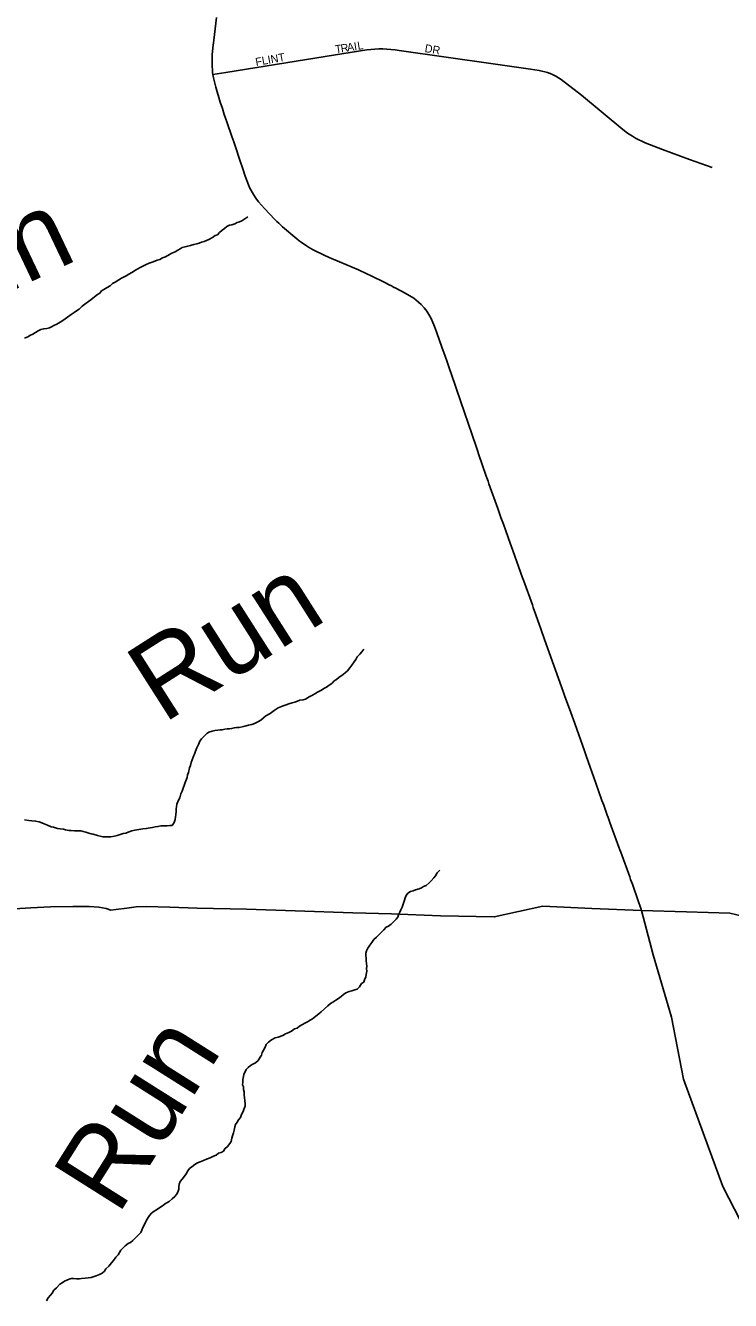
# Model space of a CAD drawing. Extents: x 0.4 to 34.4, y -2.1 to 19.9.
# Drawn here: x 4.379 to 5.213, y 12.684 to 14.193 of the extents above; entities that cross this region are included whole.
import ezdxf

# ---------------------------------------------------------------- set-up
doc = ezdxf.new("R2010")
doc.units = 0
for name, color, linetype in [('GM_X_County_Road', 7, 'Continuous'), ('GM_X_Minor_River', 7, 'Continuous'), ('GM_X_Minor_River_Text', 7, 'Continuous'), ('GM_X_State_Route', 7, 'Continuous'), ('GM_X_Township_Subdivision', 7, 'Continuous'), ('GM_X_Township_Subdivision_Text', 7, 'Continuous')]:
    doc.layers.add(name, color=color, linetype=linetype)

msp = doc.modelspace()

# ---------------------------------------------------------------- linework, layer by layer
at = {"layer": 'GM_X_County_Road'}
msp.add_lwpolyline([(4.6046, 14.2022), (4.6014, 14.1754), (4.601, 14.1723), (4.6007, 14.1693), (4.6003, 14.1662), (4.5996, 14.1578), (4.5994, 14.1452), (4.5998, 14.1392), (4.6, 14.137), (4.6004, 14.1345), (4.6011, 14.1309), (4.6038, 14.1198), (4.6091, 14.1021), (4.6117, 14.0945), (4.6139, 14.0875), (4.6154, 14.0831), (4.6174, 14.0774), (4.6229, 14.0615), (4.6251, 14.0551), (4.6271, 14.0491), (4.6318, 14.0345), (4.6361, 14.0219), (4.6385, 14.0142), (4.6424, 14.0041), (4.6437, 14.0011), (4.6452, 13.9982), (4.6467, 13.9953), (4.6484, 13.9925), (4.6513, 13.9882), (4.6544, 13.984), (4.6578, 13.9801), (4.6615, 13.9763), (4.6737, 13.963), (4.6761, 13.9607), (4.6784, 13.9586), (4.6806, 13.9566), (4.6829, 13.9546), (4.6996, 13.9401), (4.7023, 13.938), (4.7048, 13.9361), (4.711, 13.9321), (4.7137, 13.9305), (4.7191, 13.9274), (4.733, 13.9204), (4.7416, 13.9167), (4.7445, 13.9154), (4.7474, 13.9142), (4.7503, 13.913), (4.7726, 13.9034), (4.7751, 13.9023), (4.7803, 13.8999), (4.7826, 13.8988), (4.7878, 13.8965), (4.8037, 13.8886), (4.8091, 13.8858), (4.8116, 13.8845), (4.8142, 13.8832), (4.8169, 13.8819), (4.8279, 13.8761), (4.838, 13.8699), (4.841, 13.8677), (4.8438, 13.8654), (4.847, 13.8624), (4.8504, 13.8585), (4.8535, 13.8545), (4.8561, 13.8506), (4.8586, 13.8461), (4.8607, 13.8413), (4.8619, 13.8385), (4.8627, 13.8363), (4.8638, 13.8334), (4.8655, 13.8289), (4.8712, 13.8122), (4.8752, 13.8014), (4.8775, 13.7945), (4.8799, 13.7876), (4.8865, 13.7681), (4.8885, 13.7622), (4.9118, 13.6946), (4.9138, 13.6887), (4.9148, 13.6857), (4.9239, 13.6593), (4.926, 13.6534), (4.927, 13.6505), (4.9374, 13.6212), (4.9413, 13.6105), (4.9442, 13.6024), (4.947, 13.5947), (4.9521, 13.5802), (4.9552, 13.5714), (4.9669, 13.5392), (4.9679, 13.5363), (4.9784, 13.507), (4.9794, 13.5041), (4.9826, 13.4953), (4.9888, 13.4777), (4.9929, 13.466), (5.0149, 13.4045), (5.017, 13.3987), (5.0223, 13.3841), (5.0255, 13.3753), (5.0286, 13.3669), (5.04, 13.3343), (5.0421, 13.3284), (5.0534, 13.2961), (5.0607, 13.2757), (5.0617, 13.2728), (5.0628, 13.2699), (5.067, 13.2582), (5.0681, 13.2553), (5.0702, 13.2494), (5.0809, 13.2203), (5.082, 13.2173), (5.0831, 13.2144), (5.0936, 13.1851), (5.0947, 13.1822), (5.0957, 13.1793), (5.0968, 13.1764), (5.104, 13.1558), (5.106, 13.15), (5.107, 13.147), (5.1075, 13.1455), (5.1214, 13.0928), (5.143, 13.0193), (5.1572, 12.9457), (5.2037, 12.819), (5.2246, 12.7784)], dxfattribs=at)
at = {"layer": 'GM_X_Minor_River'}
for points in [[(4.5588, 13.9269), (4.5615, 13.9283), (4.5642, 13.9298), (4.5676, 13.9309), (4.5707, 13.9316), (4.5741, 13.9323), (4.578, 13.9334), (4.5814, 13.9344), (4.5841, 13.9352), (4.5868, 13.9362), (4.5899, 13.937), (4.593, 13.9384), (4.5956, 13.9395), (4.5999, 13.9417), (4.603, 13.9443), (4.6057, 13.945), (4.6084, 13.9476), (4.6115, 13.9503), (4.6142, 13.9525), (4.617, 13.9547), (4.62, 13.9562), (4.6227, 13.9569), (4.6262, 13.958), (4.6293, 13.9594), (4.632, 13.9605), (4.6347, 13.9616), (4.6381, 13.9638), (4.6416, 13.9664)], [(4.3776, 13.8225), (4.3814, 13.8243), (4.3845, 13.8262), (4.3872, 13.8273), (4.3907, 13.8295), (4.3938, 13.8313), (4.3969, 13.8328), (4.4003, 13.8339), (4.4038, 13.8342), (4.4069, 13.8349), (4.4095, 13.836), (4.4122, 13.8375), (4.4157, 13.8393), (4.4196, 13.8415), (4.4227, 13.8437), (4.4258, 13.8456), (4.4285, 13.8474), (4.4328, 13.8508), (4.4362, 13.853), (4.4389, 13.8549), (4.442, 13.8571), (4.4456, 13.8604), (4.449, 13.8631), (4.4533, 13.866), (4.456, 13.8679), (4.4603, 13.8716), (4.4638, 13.8742), (4.4665, 13.876), (4.4688, 13.8787), (4.4715, 13.8801), (4.4754, 13.8827), (4.4789, 13.8846), (4.4816, 13.8872), (4.4847, 13.889), (4.489, 13.8916), (4.4924, 13.8938), (4.4978, 13.8964), (4.5009, 13.8986), (4.5044, 13.9005), (4.5087, 13.9031), (4.5117, 13.9049), (4.5145, 13.9064), (4.5183, 13.9082), (4.5214, 13.9097), (4.5252, 13.9115), (4.5287, 13.9126), (4.5318, 13.9137), (4.5345, 13.9148), (4.5375, 13.9158), (4.5406, 13.9177), (4.5445, 13.9191), (4.5491, 13.9217), (4.5518, 13.9232), (4.5557, 13.925), (4.5588, 13.9269)], [(4.6904, 13.3899), (4.6942, 13.391), (4.6973, 13.3921), (4.7004, 13.3932), (4.7031, 13.3942), (4.7073, 13.3949), (4.71, 13.3956), (4.7142, 13.3982), (4.7181, 13.4001), (4.7212, 13.4019), (4.7243, 13.4038), (4.7289, 13.4063), (4.7316, 13.4082), (4.7347, 13.4097), (4.7378, 13.4119), (4.7413, 13.4141), (4.744, 13.4171), (4.7467, 13.4186), (4.7498, 13.4215), (4.7529, 13.4234), (4.7568, 13.4267), (4.7595, 13.429), (4.7623, 13.4324), (4.765, 13.4357), (4.7674, 13.4395), (4.7694, 13.4425), (4.7713, 13.4455), (4.7741, 13.4489), (4.7768, 13.4515), (4.7792, 13.4545)], [(4.4092, 13.2444), (4.4118, 13.244), (4.4164, 13.2424), (4.4198, 13.2419), (4.4236, 13.2415), (4.4262, 13.241), (4.43, 13.2402), (4.4327, 13.2402), (4.4365, 13.2397), (4.4411, 13.2396), (4.4441, 13.2396), (4.4468, 13.2391), (4.4502, 13.2383), (4.4536, 13.2371), (4.4563, 13.2363), (4.4589, 13.2359), (4.4638, 13.2343), (4.4669, 13.2335), (4.4703, 13.2326), (4.4733, 13.2326), (4.4771, 13.2325), (4.4798, 13.2328), (4.484, 13.2335), (4.4871, 13.2342), (4.4906, 13.2353), (4.4944, 13.2364), (4.4975, 13.2371), (4.5001, 13.2382), (4.5044, 13.2396), (4.5082, 13.2403), (4.5128, 13.2414), (4.5174, 13.242), (4.5216, 13.2423), (4.5262, 13.2434), (4.5289, 13.2437), (4.5323, 13.2444), (4.5354, 13.2448), (4.5388, 13.2455), (4.5423, 13.2458), (4.5464, 13.2457), (4.5495, 13.246), (4.5522, 13.246), (4.5545, 13.2497), (4.5558, 13.2531), (4.5562, 13.2562), (4.5567, 13.2588), (4.5568, 13.263), (4.5568, 13.2657), (4.5573, 13.2683), (4.5577, 13.2714), (4.5597, 13.2759), (4.5613, 13.2789), (4.5626, 13.2834), (4.5641, 13.2865), (4.5654, 13.2902), (4.567, 13.2944), (4.5678, 13.297), (4.5698, 13.3027), (4.5703, 13.3061), (4.5715, 13.3088), (4.5728, 13.3141), (4.574, 13.3171), (4.5748, 13.3205), (4.5757, 13.3239), (4.5769, 13.3269), (4.5789, 13.3315), (4.5797, 13.3341), (4.5813, 13.3379), (4.5833, 13.3417), (4.5849, 13.3458), (4.5869, 13.3484), (4.59, 13.3518), (4.5931, 13.3548), (4.5958, 13.3563), (4.5997, 13.3577), (4.6028, 13.3584), (4.6062, 13.3587), (4.6089, 13.3591), (4.6115, 13.3594), (4.6146, 13.3601), (4.6173, 13.3604), (4.62, 13.3604), (4.6226, 13.3607), (4.6257, 13.3614), (4.6284, 13.3621), (4.6314, 13.3621), (4.6349, 13.3628), (4.6383, 13.3635), (4.6426, 13.3649), (4.6464, 13.3656), (4.6498, 13.3667), (4.6537, 13.3685), (4.6572, 13.3707), (4.6603, 13.3733), (4.663, 13.3756), (4.668, 13.3785), (4.6731, 13.3822), (4.6777, 13.3852), (4.6835, 13.3878), (4.6873, 13.3888), (4.6904, 13.3899)], [(4.3777, 13.2526), (4.3827, 13.2521), (4.3861, 13.2517), (4.3906, 13.2512), (4.3948, 13.2504), (4.3982, 13.2492), (4.4009, 13.248), (4.4046, 13.2464), (4.4092, 13.2444)], [(4.6366, 12.9336), (4.6367, 12.9366), (4.6356, 12.9393), (4.6357, 12.9424), (4.6358, 12.9454), (4.6366, 12.9492), (4.637, 12.9519), (4.6386, 12.9545), (4.6398, 12.9571), (4.6422, 12.9598), (4.6449, 12.962), (4.6476, 12.9635), (4.6507, 12.9653), (4.6538, 12.9679), (4.6562, 12.9717), (4.6578, 12.9743), (4.6586, 12.9773), (4.6602, 12.98), (4.6622, 12.9837), (4.6634, 12.9868), (4.6661, 12.9898), (4.6696, 12.9924), (4.6742, 12.9949), (4.6777, 12.9956), (4.6831, 12.9974), (4.6865, 12.9993), (4.6904, 13.0011), (4.6935, 13.0026), (4.697, 13.0055), (4.7, 13.0063), (4.7028, 13.0085), (4.7066, 13.0107), (4.7093, 13.0122), (4.7124, 13.0136), (4.7155, 13.0155), (4.7182, 13.0173), (4.7221, 13.0203), (4.7256, 13.0233), (4.7287, 13.0255), (4.7326, 13.0289), (4.7365, 13.0326), (4.7396, 13.0352), (4.7423, 13.0371), (4.7458, 13.0393), (4.7489, 13.0415), (4.752, 13.0437), (4.7551, 13.046), (4.7578, 13.0482), (4.7616, 13.0496), (4.7647, 13.0503), (4.7682, 13.0514), (4.7712, 13.0525), (4.774, 13.0551), (4.7763, 13.0589), (4.779, 13.0607), (4.7799, 13.0634), (4.7815, 13.0668), (4.7819, 13.0698), (4.7824, 13.0736), (4.7821, 13.0767), (4.7825, 13.0797), (4.7822, 13.0827), (4.7819, 13.0858), (4.7816, 13.0892), (4.7813, 13.0923), (4.7813, 13.0949), (4.7822, 13.0976), (4.7838, 13.101), (4.7861, 13.1044), (4.7885, 13.1077), (4.7909, 13.1111), (4.794, 13.1137), (4.7971, 13.1171), (4.8002, 13.1201), (4.8026, 13.1227), (4.8053, 13.1257), (4.808, 13.1268), (4.8115, 13.1294), (4.8146, 13.1324), (4.8173, 13.135), (4.8193, 13.1376), (4.8201, 13.1403), (4.8217, 13.1433), (4.8229, 13.1463), (4.8245, 13.1493), (4.8258, 13.1542), (4.827, 13.1576), (4.8278, 13.1603), (4.829, 13.1633), (4.831, 13.1659), (4.8341, 13.1678), (4.8375, 13.1688), (4.8402, 13.1699), (4.8444, 13.171), (4.8471, 13.1721), (4.8498, 13.1739), (4.8529, 13.175), (4.8564, 13.178), (4.8588, 13.1806), (4.8619, 13.184), (4.8639, 13.1866)], [(4.8639, 13.1866), (4.8658, 13.19), (4.869, 13.193)], [(4.4034, 12.6837), (4.4054, 12.6871), (4.4081, 12.6901), (4.4101, 12.6928), (4.4124, 12.6961), (4.4152, 12.6991), (4.4194, 12.7032), (4.4221, 12.7047), (4.4249, 12.7069), (4.4276, 12.708), (4.4303, 12.7091), (4.4329, 12.7098), (4.4356, 12.7098), (4.439, 12.7097), (4.4425, 12.7097), (4.4451, 12.71), (4.4493, 12.7103), (4.4528, 12.7106), (4.4562, 12.7113), (4.4589, 12.712), (4.4624, 12.7131), (4.4662, 12.7149), (4.4693, 12.7164), (4.472, 12.7186), (4.4736, 12.7213), (4.4771, 12.7246), (4.4806, 12.7284), (4.483, 12.7314), (4.4857, 12.7351), (4.4885, 12.7381), (4.4901, 12.7407), (4.4916, 12.7434), (4.494, 12.746), (4.4967, 12.7486), (4.5002, 12.7512), (4.5029, 12.7527), (4.5056, 12.7549), (4.5091, 12.7583), (4.5123, 12.7616), (4.515, 12.7646), (4.5162, 12.7673), (4.5174, 12.7703), (4.5194, 12.7737), (4.5214, 12.7782), (4.5238, 12.782), (4.5254, 12.7846), (4.5277, 12.7872), (4.5308, 12.7895), (4.5335, 12.7913), (4.5366, 12.7932), (4.5409, 12.7961), (4.5444, 12.7987), (4.5486, 12.8009), (4.5521, 12.8043), (4.5552, 12.8069), (4.5572, 12.8095), (4.5588, 12.8122), (4.56, 12.8156), (4.5601, 12.8182), (4.5605, 12.8216), (4.5617, 12.8247), (4.5641, 12.8277), (4.5668, 12.831), (4.5688, 12.834), (4.5708, 12.8374), (4.5728, 12.84), (4.5755, 12.8423), (4.579, 12.8449), (4.5821, 12.8467), (4.5855, 12.8482), (4.5894, 12.8496), (4.5928, 12.8511), (4.5971, 12.8529), (4.6013, 12.8547), (4.6044, 12.8558), (4.6071, 12.8581), (4.6102, 12.8591), (4.6129, 12.8606), (4.6145, 12.8636), (4.6176, 12.8662), (4.6203, 12.8696), (4.6219, 12.8722), (4.6227, 12.876), (4.6236, 12.8787), (4.6248, 12.8825), (4.6256, 12.8855), (4.6265, 12.8893), (4.6273, 12.8923), (4.6293, 12.8949), (4.6309, 12.8976), (4.6332, 12.9006), (4.6341, 12.904), (4.6364, 12.9077), (4.6376, 12.9111), (4.6385, 12.9138), (4.6385, 12.9168), (4.6382, 12.9203), (4.6379, 12.9241), (4.6376, 12.9271), (4.6373, 12.9309), (4.6366, 12.9336)]]:
    msp.add_lwpolyline(points, dxfattribs=at)
at = {"layer": 'GM_X_State_Route'}
msp.add_lwpolyline([(4.3657, 13.1474), (4.385, 13.1487), (4.4081, 13.1496), (4.4346, 13.1501), (4.454, 13.1503), (4.4653, 13.1494), (4.474, 13.1478), (4.4797, 13.1459), (4.4854, 13.1466), (4.4986, 13.1483), (4.5096, 13.1498), (4.5214, 13.15), (4.5494, 13.1493), (4.5819, 13.1483), (4.6402, 13.1469), (4.6978, 13.1452), (4.7659, 13.1426), (4.8117, 13.1414), (4.8697, 13.1393), (4.9333, 13.1379), (4.9907, 13.1504), (5.0487, 13.148), (5.1075, 13.1455), (5.1606, 13.144), (5.2119, 13.1424), (5.2521, 13.1328)], dxfattribs=at)
at = {"layer": 'GM_X_Township_Subdivision'}
msp.add_lwpolyline([(4.6004, 14.1345), (4.6156, 14.137), (4.7456, 14.158), (4.7824, 14.1639), (4.7871, 14.1644), (4.7919, 14.1648), (4.7967, 14.165), (4.8014, 14.1649), (4.8063, 14.1648), (4.8111, 14.1644), (4.816, 14.1639), (4.8208, 14.1631), (4.9321, 14.1473), (4.9761, 14.1409), (4.9864, 14.1393), (4.9898, 14.1387), (4.9931, 14.1379), (4.9964, 14.1369), (4.9996, 14.1358), (5.0029, 14.1343), (5.0061, 14.1327), (5.0092, 14.1309), (5.0123, 14.1289), (5.0365, 14.1101), (5.0856, 14.0695), (5.0911, 14.0654), (5.0968, 14.0617), (5.1004, 14.0595), (5.1042, 14.0575), (5.1079, 14.0556), (5.1118, 14.0538), (5.1323, 14.046), (5.1642, 14.0342), (5.191, 14.0247)], dxfattribs=at)

# ---------------------------------------------------------------- texts
at = {"layer": 'GM_X_Minor_River_Text'}
for rotation, p in [(25.4036, (4.2326, 13.8167)), (32.5105, (4.5416, 13.3658)), (57.7489, (4.4879, 12.7835))]:
    msp.add_text('Run', height=0.0947, rotation=rotation, dxfattribs=at).set_placement(p)
at = {"layer": 'GM_X_Township_Subdivision_Text'}
for s, rotation, p in [('T', 8.8334, (4.7458, 14.1597)), ('R', 8.8034, (4.7524, 14.1607)), ('A', 8.8334, (4.7598, 14.1619)), ('I', 8.8226, (4.768, 14.1631)), ('L', 8.8064, (4.7721, 14.1638)), ('DR', 350.5436, (4.8505, 14.1613)), ('FLINT', 10.1751, (4.6516, 14.1447))]:
    msp.add_text(s, height=0.00947, rotation=rotation, dxfattribs=at).set_placement(p)

doc.saveas('drawing.dxf')
